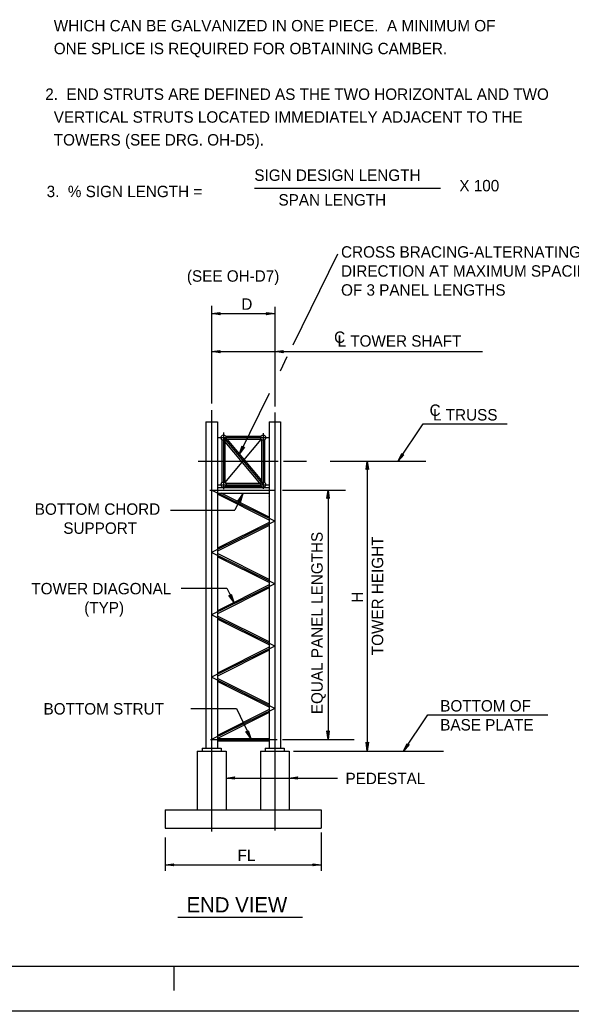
# Model space of a CAD drawing. Extents: x -3 to 26050223, y 0 to 12035012.
# Drawn here: x 31.01 to 43.09, y 0 to 21.72 of the extents above; entities that cross this region are included whole.
import ezdxf

# ---------------------------------------------------------------- set-up
doc = ezdxf.new("R2010")
doc.units = 0
for name, color, linetype in [('1', 7, 'Continuous'), ('2', 7, 'Continuous'), ('39', 7, 'Continuous')]:
    doc.layers.add(name, color=color, linetype=linetype)

msp = doc.modelspace()

# ---------------------------------------------------------------- linework, layer by layer
at = {"layer": '1'}
for p, q in [((36.149, 18.027), (40.227, 18.027)), ((37.973, 16.581), (36.988, 14.589)), ((35.213, 15.448), (35.213, 13.314)), ((36.596, 15.431), (36.596, 13.248)), ((35.213, 15.281), (36.596, 15.281)), ((35.213, 14.448), (36.596, 14.448)), ((36.596, 14.448), (41.146, 14.448)), ((36.863, 14.331), (36.713, 14.023)), ((36.471, 13.531), (35.821, 12.206)), ((35.213, 13.164), (35.213, 3.939)), ((36.596, 13.114), (36.596, 3.956)), ((35.088, 12.906), (35.088, 5.764)), ((35.088, 12.906), (35.338, 12.906)), ((35.338, 12.906), (35.338, 5.764)), ((36.471, 12.906), (36.471, 5.764)), ((36.471, 12.906), (36.721, 12.906)), ((36.721, 12.906), (36.721, 5.764)), ((39.296, 12.048), (39.846, 12.864)), ((39.846, 12.864), (41.688, 12.864)), ((35.471, 12.673), (35.471, 11.431)), ((35.521, 12.598), (36.288, 12.598)), ((36.338, 12.664), (36.338, 11.439)), ((35.338, 12.564), (36.471, 12.564)), ((35.438, 12.514), (35.438, 11.581)), ((35.471, 12.564), (36.338, 11.531)), ((35.505, 11.573), (36.296, 12.523)), ((35.505, 12.514), (35.505, 11.581)), ((35.505, 12.473), (36.263, 11.564)), ((35.521, 12.531), (36.288, 12.531)), ((35.546, 12.531), (36.305, 11.623)), ((36.305, 12.514), (36.305, 11.581)), ((36.371, 12.514), (36.371, 11.581)), ((34.921, 12.048), (35.58, 12.048)), ((35.046, 12.048), (36.671, 12.048)), ((36.788, 12.048), (37.288, 12.048)), ((37.813, 12.048), (39.905, 12.048)), ((37.838, 12.048), (37.955, 12.048)), ((38.621, 12.048), (38.621, 5.698)), ((35.338, 11.531), (36.471, 11.531)), ((35.521, 11.564), (36.288, 11.564)), ((35.171, 11.414), (36.605, 11.414)), ((36.596, 10.731), (35.213, 11.414)), ((35.338, 11.473), (36.471, 11.473)), ((35.338, 11.348), (36.471, 11.348)), ((36.471, 10.756), (35.338, 11.323)), ((36.471, 10.823), (35.421, 11.348)), ((35.521, 11.498), (36.288, 11.498)), ((35.905, 11.348), (35.721, 10.973)), ((36.763, 11.414), (38.146, 11.414)), ((37.763, 11.414), (37.763, 5.948)), ((36.455, 11.281), (36.455, 11.281)), ((36.455, 11.281), (36.455, 11.281)), ((34.313, 10.973), (35.721, 10.973)), ((36.596, 10.731), (35.213, 10.048)), ((36.471, 10.706), (35.338, 10.139)), ((36.471, 10.639), (35.338, 10.073)), ((36.596, 9.364), (35.213, 10.048)), ((36.471, 9.456), (35.338, 10.023)), ((36.471, 9.389), (35.338, 9.956)), ((36.596, 9.364), (35.213, 8.681)), ((36.471, 9.339), (35.338, 8.773)), ((34.546, 9.264), (35.546, 9.264)), ((36.471, 9.273), (35.338, 8.706)), ((35.546, 9.264), (35.696, 8.956)), ((36.596, 7.998), (35.213, 8.681)), ((36.471, 8.089), (35.338, 8.656)), ((36.471, 8.023), (35.338, 8.589)), ((36.596, 7.998), (35.213, 7.314)), ((36.471, 7.973), (35.338, 7.406)), ((36.471, 7.906), (35.338, 7.339)), ((36.596, 6.631), (35.213, 7.314)), ((36.471, 6.723), (35.338, 7.289)), ((36.471, 6.656), (35.338, 7.223)), ((34.755, 6.631), (35.755, 6.631)), ((36.596, 6.631), (35.213, 5.948)), ((36.471, 6.606), (35.338, 6.039)), ((36.471, 6.539), (35.338, 5.973)), ((35.755, 6.631), (36.071, 5.973)), ((39.413, 5.698), (39.946, 6.489)), ((39.946, 6.489), (42.58, 6.489)), ((35.188, 5.948), (36.646, 5.948)), ((35.338, 5.973), (36.471, 5.973)), ((35.338, 5.923), (36.471, 5.923)), ((36.763, 5.948), (38.338, 5.948)), ((34.896, 5.698), (34.896, 4.414)), ((34.896, 5.698), (35.53, 5.698)), ((35.005, 5.764), (35.005, 5.698)), ((35.005, 5.764), (35.421, 5.764)), ((35.421, 5.764), (35.421, 5.698)), ((35.53, 5.698), (35.53, 4.414)), ((36.28, 5.698), (36.28, 4.414)), ((36.28, 5.698), (36.913, 5.698)), ((36.388, 5.764), (36.388, 5.698)), ((36.388, 5.764), (36.805, 5.764)), ((36.805, 5.764), (36.805, 5.698)), ((36.913, 5.698), (36.913, 4.414)), ((37.005, 5.698), (40.296, 5.698)), ((35.53, 5.106), (37.971, 5.106)), ((34.196, 4.414), (34.196, 4.006)), ((34.196, 4.414), (37.613, 4.414)), ((37.613, 4.414), (37.613, 4.006)), ((34.196, 4.006), (37.613, 4.006)), ((37.613, 3.914), (37.613, 3.073)), ((34.196, 3.806), (34.196, 3.073)), ((37.613, 3.848), (37.613, 3.773)), ((34.196, 3.206), (37.613, 3.206)), ((3.6, 0.983), (68.183, 0.983)), ((34.392, 0.45), (34.392, 0.983)), ((68.892, 0), (0, 0))]:
    msp.add_line(p, q, dxfattribs=at)
for points in [[(38.596, 11.864), (38.621, 12.048), (38.646, 11.864), (38.621, 11.881)], [(35.905, 11.348), (35.78, 11.173), (35.838, 11.206), (35.846, 11.139)], [(37.738, 11.231), (37.763, 11.414), (37.788, 11.231), (37.763, 11.248)], [(35.621, 9.106), (35.638, 9.131), (35.696, 8.956), (35.588, 9.106)], [(37.788, 6.139), (37.763, 5.948), (37.738, 6.139), (37.763, 6.114)], [(38.646, 5.889), (38.621, 5.698), (38.596, 5.889), (38.621, 5.864)], [(39.505, 5.839), (39.538, 5.839), (39.413, 5.698), (39.496, 5.864)], [(37.08, 5.106), (37.096, 5.081), (36.913, 5.106), (37.096, 5.131)], [(34.388, 3.181), (34.196, 3.206), (34.388, 3.231), (34.363, 3.206)], [(37.43, 3.231), (37.613, 3.206), (37.43, 3.181), (37.446, 3.206)]]:
    msp.add_lwpolyline(points, close=True, dxfattribs=at)
for centre in [(35.475, 12.564), (36.341, 12.564), (35.475, 11.531), (36.341, 11.531)]:
    msp.add_circle(centre, 0.0583, dxfattribs=at)
at = {"layer": '2'}
msp.add_line((34.471, 2.056), (37.205, 2.056), dxfattribs=at)
at = {"layer": '39'}
for points in [[(35.38, 15.281), (35.396, 15.256), (35.213, 15.281), (35.396, 15.306)], [(36.43, 15.281), (36.413, 15.306), (36.596, 15.281), (36.413, 15.256)], [(35.38, 14.448), (35.396, 14.423), (35.213, 14.448), (35.396, 14.473)], [(36.763, 14.448), (36.78, 14.423), (36.596, 14.448), (36.78, 14.473)], [(35.896, 12.356), (35.93, 12.356), (35.821, 12.206), (35.88, 12.381)], [(39.388, 12.189), (39.421, 12.189), (39.296, 12.048), (39.38, 12.214)], [(35.996, 6.123), (36.013, 6.148), (36.071, 5.973), (35.963, 6.123)], [(35.696, 5.106), (35.713, 5.081), (35.53, 5.106), (35.713, 5.131)]]:
    msp.add_lwpolyline(points, close=True, dxfattribs=at)

# ---------------------------------------------------------------- texts
at = {"layer": '1'}
for s, p in [('D', (35.863, 15.364)), ('TOWER DIAGONAL', (31.263, 9.131)), ('(TYP)', (32.421, 8.714)), ('BOTTOM STRUT', (31.53, 6.498)), ('FL', (35.78, 3.289))]:
    msp.add_text(s, height=0.25, dxfattribs=at).set_placement(p)
at = {"layer": '2'}
for s, height, p in [('  WHICH CAN BE GALVANIZED IN ONE PIECE.  A MINIMUM OF', 0.25, (31.568, 21.462)), ('  ONE SPLICE IS REQUIRED FOR OBTAINING CAMBER.', 0.25, (31.568, 20.962)), ('2.  END STRUTS ARE DEFINED AS THE TWO HORIZONTAL AND TWO', 0.25, (31.568, 19.962)), ('  VERTICAL STRUTS LOCATED IMMEDIATELY ADJACENT TO THE', 0.25, (31.568, 19.462)), ('  TOWERS (SEE DRG. OH-D5).', 0.25, (31.568, 18.962)), ('SIGN DESIGN LENGTH', 0.25, (36.148, 18.188)), ('3.  % SIGN LENGTH = ', 0.25, (31.598, 17.831)), ('X 100', 0.25, (40.64, 17.958)), ('SPAN LENGTH', 0.25, (36.677, 17.647)), ('CROSS BRACING-ALTERNATING IN', 0.25, (38.048, 16.506)), ('DIRECTION AT MAXIMUM SPACING', 0.25, (38.048, 16.089)), (' (SEE OH-D7)', 0.25, (34.578, 15.979)), ('OF 3 PANEL LENGTHS', 0.25, (38.048, 15.673)), ('C', 0.25, (37.896, 14.639)), ('L TOWER SHAFT', 0.25, (37.971, 14.556)), ('C', 0.25, (39.988, 13.039)), ('L TRUSS', 0.25, (40.063, 12.939)), ('BOTTOM CHORD', 0.25, (31.338, 10.873)), ('SUPPORT', 0.25, (31.963, 10.456)), ('BOTTOM OF', 0.25, (40.221, 6.564)), ('BASE PLATE', 0.25, (40.221, 6.148)), ('PEDESTAL', 0.25, (38.146, 4.973)), ('END VIEW', 0.3334, (34.663, 2.164))]:
    msp.add_text(s, height=height, dxfattribs=at).set_placement(p)
for s, p in [('EQUAL PANEL LENGTHS', (37.646, 6.506)), ('TOWER HEIGHT', (38.971, 7.798)), ('H', (38.53, 8.948))]:
    msp.add_text(s, height=0.25, rotation=90, dxfattribs=at).set_placement(p)

doc.saveas('drawing.dxf')
